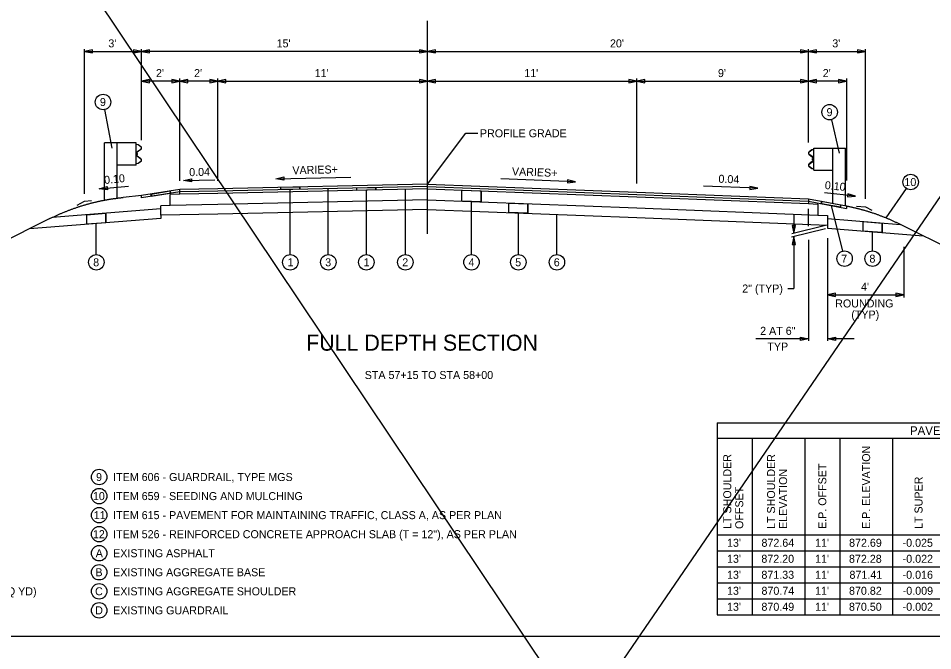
# Model space of a CAD drawing. Extents: x -345 to 102, y -108 to 100.
# Drawn here: x -306.37 to -258.37, y -8.45 to 24.76 of the extents above; entities that cross this region are included whole.
import ezdxf

# ---------------------------------------------------------------- set-up
doc = ezdxf.new("R2010")
doc.units = 0
for name, color, linetype in [('RD_P_Cells', 7, 'Continuous'), ('SH_Border', 7, 'Continuous'), ('SH_Data', 7, 'Continuous'), ('SH_Text', 7, 'Continuous'), ('TX_P_1', 7, 'Continuous'), ('TX_X_1', 7, 'Continuous'), ('XS_P_Finished_Grade', 7, 'Continuous'), ('XS_P_Pavt_Surface', 7, 'Continuous')]:
    doc.layers.add(name, color=color, linetype=linetype)

msp = doc.modelspace()

# ---------------------------------------------------------------- linework, layer by layer
at = {"layer": 'RD_P_Cells'}
for p, q in [((-301.175, 18.213), (-301.842, 18.213)), ((-301.842, 15.21), (-301.842, 18.213)), ((-300.175, 18.213), (-301.175, 18.213)), ((-301.175, 15.315), (-301.175, 18.213)), ((-300.175, 17.046), (-300.175, 18.213)), ((-300.16, 18.141), (-300.16, 18.141)), ((-300.16, 18.141), (-300.073, 18.126)), ((-300.16, 18.131), (-300.16, 18.141)), ((-300.16, 18.131), (-300.16, 18.131)), ((-300.077, 18.117), (-300.16, 18.131)), ((-300.123, 17.747), (-299.936, 17.885)), ((-299.93, 17.877), (-300.117, 17.739)), ((-300.077, 18.117), (-300.077, 18.117)), ((-299.936, 18.011), (-300.077, 18.117)), ((-300.073, 18.126), (-300.073, 18.126)), ((-300.073, 18.126), (-299.93, 18.019)), ((-300.056, 17.797), (-300.056, 17.797)), ((-300.055, 18.101), (-300.055, 18.101)), ((-300.05, 18.109), (-300.05, 18.109)), ((-300.05, 17.789), (-300.05, 17.789)), ((-299.936, 18.011), (-299.936, 18.011)), ((-299.936, 17.885), (-299.936, 17.885)), ((-299.93, 18.019), (-299.93, 18.019)), ((-299.93, 17.877), (-299.93, 17.877)), ((-299.904, 17.948), (-299.904, 17.948)), ((-299.894, 17.948), (-299.894, 17.948)), ((-264.715, 17.856), (-264.859, 17.749)), ((-264.853, 17.741), (-264.711, 17.847)), ((-264.739, 17.838), (-264.739, 17.838)), ((-264.733, 17.831), (-264.733, 17.831)), ((-264.628, 17.871), (-264.715, 17.856)), ((-264.715, 17.856), (-264.715, 17.856)), ((-264.711, 17.847), (-264.628, 17.861)), ((-264.711, 17.847), (-264.711, 17.847)), ((-264.628, 17.871), (-264.628, 17.871)), ((-264.628, 17.861), (-264.628, 17.871)), ((-264.628, 17.861), (-264.628, 17.861)), ((-264.613, 17.943), (-263.613, 17.943)), ((-264.613, 16.776), (-264.613, 17.943)), ((-263.613, 17.943), (-262.946, 17.943)), ((-263.613, 15.038), (-263.613, 17.943)), ((-262.946, 14.913), (-262.946, 17.943)), ((-300.159, 17.676), (-300.159, 17.676)), ((-300.159, 17.584), (-300.159, 17.676)), ((-300.159, 17.598), (-300.159, 17.661)), ((-300.159, 17.584), (-300.159, 17.584)), ((-300.15, 17.676), (-300.15, 17.676)), ((-300.15, 17.676), (-300.149, 17.584)), ((-300.149, 17.598), (-300.149, 17.661)), ((-300.149, 17.584), (-300.149, 17.584)), ((-300.123, 17.747), (-300.123, 17.747)), ((-300.123, 17.512), (-300.123, 17.512)), ((-299.935, 17.375), (-300.123, 17.512)), ((-300.117, 17.739), (-300.117, 17.739)), ((-300.117, 17.52), (-300.117, 17.52)), ((-300.117, 17.52), (-299.929, 17.383)), ((-299.935, 17.375), (-299.935, 17.375)), ((-299.929, 17.383), (-299.929, 17.383)), ((-299.903, 17.312), (-299.903, 17.312)), ((-299.893, 17.312), (-299.893, 17.312)), ((-264.894, 17.678), (-264.894, 17.678)), ((-264.884, 17.678), (-264.884, 17.678)), ((-264.859, 17.749), (-264.859, 17.749)), ((-264.858, 17.606), (-264.858, 17.606)), ((-264.858, 17.606), (-264.671, 17.469)), ((-264.853, 17.741), (-264.853, 17.741)), ((-264.852, 17.614), (-264.852, 17.614)), ((-264.665, 17.477), (-264.852, 17.614)), ((-264.738, 17.518), (-264.738, 17.518)), ((-264.732, 17.526), (-264.732, 17.526)), ((-264.671, 17.469), (-264.671, 17.469)), ((-264.665, 17.477), (-264.665, 17.477)), ((-264.639, 17.405), (-264.639, 17.405)), ((-264.639, 17.405), (-264.639, 17.313)), ((-264.639, 17.328), (-264.639, 17.391)), ((-264.639, 17.313), (-264.639, 17.313)), ((-264.629, 17.405), (-264.629, 17.405)), ((-264.629, 17.313), (-264.629, 17.405)), ((-264.629, 17.328), (-264.629, 17.391)), ((-264.629, 17.313), (-264.629, 17.313)), ((-300.175, 17.046), (-301.175, 17.046)), ((-300.158, 17.128), (-300.075, 17.143)), ((-300.071, 17.133), (-300.158, 17.118)), ((-300.158, 17.128), (-300.158, 17.128)), ((-300.158, 17.118), (-300.158, 17.128)), ((-300.158, 17.118), (-300.158, 17.118)), ((-300.075, 17.143), (-299.934, 17.249)), ((-299.928, 17.241), (-300.071, 17.133)), ((-299.934, 17.249), (-299.934, 17.249)), ((-299.928, 17.241), (-299.928, 17.241)), ((-264.895, 17.042), (-264.895, 17.042)), ((-264.885, 17.042), (-264.885, 17.042)), ((-264.86, 16.971), (-264.86, 16.971)), ((-264.86, 16.971), (-264.717, 16.863)), ((-264.671, 17.25), (-264.859, 17.113)), ((-264.859, 17.113), (-264.859, 17.113)), ((-264.854, 16.978), (-264.854, 16.978)), ((-264.713, 16.872), (-264.854, 16.978)), ((-264.853, 17.105), (-264.665, 17.242)), ((-264.853, 17.105), (-264.853, 17.105)), ((-264.717, 16.863), (-264.63, 16.848)), ((-264.63, 16.858), (-264.713, 16.872)), ((-264.671, 17.25), (-264.671, 17.25)), ((-264.665, 17.242), (-264.665, 17.242)), ((-264.63, 16.858), (-264.63, 16.858)), ((-264.63, 16.848), (-264.63, 16.858)), ((-264.63, 16.848), (-264.63, 16.848)), ((-264.613, 16.776), (-263.613, 16.776))]:
    msp.add_line(p, q, dxfattribs=at)
for points in [[(-300.141, 17.69), (-300.141, 17.57), (-300.149, 17.57), (-300.149, 17.69)], [(-300.141, 17.658), (-300.141, 17.6), (-300.116, 17.6), (-300.116, 17.658)], [(-264.647, 17.388), (-264.647, 17.329), (-264.672, 17.329), (-264.672, 17.388)], [(-264.647, 17.419), (-264.647, 17.299), (-264.639, 17.299), (-264.639, 17.419)]]:
    msp.add_lwpolyline(points, close=True, dxfattribs=at)
for centre, radius, start, end in [((-299.983, 17.948), 0.0787, 306.318, 53.2212), ((-299.983, 17.948), 0.0886, 306.318, 53.2212), ((-300.071, 17.676), 0.0886, 126.318, 180.0944), ((-300.071, 17.584), 0.0886, 180.0944, 233.8707), ((-300.071, 17.676), 0.0788, 126.318, 180.0944), ((-300.071, 17.584), 0.0788, 180.0944, 233.8707), ((-299.982, 17.312), 0.0787, 306.9675, 53.8707), ((-299.982, 17.312), 0.0886, 306.9675, 53.8707), ((-264.805, 17.678), 0.0886, 126.7788, 233.682), ((-264.805, 17.678), 0.0787, 126.7788, 233.682), ((-264.717, 17.405), 0.0788, 359.9056, 53.682), ((-264.718, 17.314), 0.0788, 306.1293, 359.9056), ((-264.717, 17.405), 0.0886, 359.9056, 53.682), ((-264.718, 17.314), 0.0886, 306.1293, 359.9056), ((-264.807, 17.041), 0.0886, 126.1293, 233.0325), ((-264.807, 17.041), 0.0787, 126.1293, 233.0325)]:
    msp.add_arc(centre, radius, start, end, dxfattribs=at)
at = {"layer": 'SH_Border'}
msp.add_lwpolyline([(-330.644, 55.298), (-234.644, 55.298), (-234.644, -7.702), (-330.644, -7.702)], close=True, dxfattribs=at)
at = {"layer": 'TX_P_1'}
for p, q in [((-302.894, 15.533), (-302.894, 23.137)), ((-302.474, 22.938), (-302.474, 23.106)), ((-300.314, 23.106), (-300.314, 22.938)), ((-299.894, 18.358), (-299.894, 23.137)), ((-299.474, 22.938), (-299.474, 23.106)), ((-285.314, 23.106), (-285.314, 22.938)), ((-284.474, 22.938), (-284.474, 23.106)), ((-265.314, 23.106), (-265.314, 22.938)), ((-264.894, 18.228), (-264.894, 23.137)), ((-264.474, 22.938), (-264.474, 23.106)), ((-262.314, 23.106), (-262.314, 22.938)), ((-261.894, 15.285), (-261.894, 23.137)), ((-302.894, 23.022), (-299.894, 23.022)), ((-284.894, 23.022), (-299.894, 23.022)), ((-284.894, 23.022), (-264.894, 23.022)), ((-264.894, 23.022), (-261.894, 23.022)), ((-297.894, 21.462), (-299.894, 21.462)), ((-299.474, 21.378), (-299.474, 21.546)), ((-298.314, 21.546), (-298.314, 21.378)), ((-297.894, 16.216), (-297.894, 21.591)), ((-295.894, 21.462), (-297.894, 21.462)), ((-297.474, 21.378), (-297.474, 21.546)), ((-296.314, 21.546), (-296.314, 21.378)), ((-295.894, 16.231), (-295.894, 21.591)), ((-295.894, 21.462), (-284.894, 21.462)), ((-295.474, 21.378), (-295.474, 21.546)), ((-285.314, 21.546), (-285.314, 21.378)), ((-285.314, 21.546), (-285.314, 21.378)), ((-284.894, 21.462), (-273.894, 21.462)), ((-284.474, 21.378), (-284.474, 21.546)), ((-274.314, 21.546), (-274.314, 21.378)), ((-274.314, 21.546), (-274.314, 21.378)), ((-273.894, 16.086), (-273.894, 21.591)), ((-273.894, 21.462), (-264.894, 21.462)), ((-273.474, 21.378), (-273.474, 21.546)), ((-265.314, 21.546), (-265.314, 21.378)), ((-262.894, 21.462), (-264.894, 21.462)), ((-264.474, 21.378), (-264.474, 21.546)), ((-263.314, 21.546), (-263.314, 21.378)), ((-262.894, 21.591), (-262.894, 16.245)), ((-284.894, 16.054), (-282.875, 18.72)), ((-282.875, 18.72), (-282.25, 18.72)), ((-297.28, 16.331), (-297.277, 16.163)), ((-292.848, 16.337), (-288.92, 16.424)), ((-292.429, 16.43), (-292.426, 16.262)), ((-277.119, 16.179), (-281.045, 16.328)), ((-302.12, 15.796), (-300.585, 15.949)), ((-301.711, 15.921), (-301.694, 15.754)), ((-297.698, 16.239), (-296.05, 16.272)), ((-277.535, 16.279), (-277.542, 16.111)), ((-267.548, 15.833), (-270.402, 15.948)), ((-267.964, 15.934), (-267.971, 15.766)), ((-262.414, 15.422), (-264.051, 15.586)), ((-262.823, 15.548), (-262.84, 15.381)), ((-298.894, 14.754), (-304.59, 14.298)), ((-298.894, 14.419), (-298.894, 14.252)), ((-265.664, 14.438), (-265.664, 13.465)), ((-264.894, 13.838), (-264.894, 14.747)), ((-298.894, 14.252), (-305.787, 13.701)), ((-263.894, 14.238), (-260.053, 13.931)), ((-264.003, 13.709), (-265.778, 13.27)), ((-264.003, 13.876), (-265.757, 13.441)), ((-265.58, 13.885), (-265.748, 13.885)), ((-263.894, 13.903), (-263.894, 13.736)), ((-263.894, 13.736), (-258.858, 13.334)), ((-265.664, 13.298), (-265.664, 10.569)), ((-264.894, 13.133), (-264.894, 7.819)), ((-263.894, 13.212), (-263.894, 7.819)), ((-265.748, 12.878), (-265.58, 12.878)), ((-259.894, 12.76), (-259.894, 10.097)), ((-265.983, 10.569), (-265.664, 10.569)), ((-263.894, 10.241), (-259.894, 10.241)), ((-263.474, 10.157), (-263.474, 10.325)), ((-260.314, 10.325), (-260.314, 10.157)), ((-264.894, 7.926), (-267.663, 7.926)), ((-265.314, 7.842), (-265.314, 8.01)), ((-262.492, 7.926), (-263.894, 7.926)), ((-263.474, 8.01), (-263.474, 7.842)), ((-269.689, 3.507), (-269.689, -6.564)), ((-269.689, 3.507), (-240.289, 3.507)), ((-269.689, 2.707), (-240.289, 2.707)), ((-267.839, 2.707), (-267.839, -6.564)), ((-265.089, 2.707), (-265.089, -6.564)), ((-263.239, 2.707), (-263.239, -6.564)), ((-260.489, 2.707), (-260.489, -6.564)), ((-269.689, -2.364), (-240.289, -2.364)), ((-269.689, -3.204), (-240.289, -3.204)), ((-269.689, -4.044), (-240.289, -4.044)), ((-269.689, -4.884), (-240.289, -4.884)), ((-269.689, -5.724), (-240.289, -5.724)), ((-269.689, -6.564), (-240.289, -6.564))]:
    msp.add_line(p, q, dxfattribs=at)
for points in [[(-302.474, 23.106), (-302.894, 23.022), (-302.474, 22.938)], [(-300.314, 22.938), (-299.894, 23.022), (-300.314, 23.106)], [(-299.474, 23.106), (-299.894, 23.022), (-299.474, 22.938)], [(-285.314, 22.938), (-284.894, 23.022), (-285.314, 23.106)], [(-284.474, 23.106), (-284.894, 23.022), (-284.474, 22.938)], [(-265.314, 22.938), (-264.894, 23.022), (-265.314, 23.106)], [(-264.474, 23.106), (-264.894, 23.022), (-264.474, 22.938)], [(-262.314, 22.938), (-261.894, 23.022), (-262.314, 23.106)], [(-299.474, 21.546), (-299.894, 21.462), (-299.474, 21.378)], [(-298.314, 21.378), (-297.894, 21.462), (-298.314, 21.546)], [(-297.474, 21.546), (-297.894, 21.462), (-297.474, 21.378)], [(-296.314, 21.378), (-295.894, 21.462), (-296.314, 21.546)], [(-295.474, 21.546), (-295.894, 21.462), (-295.474, 21.378)], [(-285.314, 21.378), (-284.894, 21.462), (-285.314, 21.546)], [(-285.314, 21.378), (-284.894, 21.462), (-285.314, 21.546)], [(-284.474, 21.546), (-284.894, 21.462), (-284.474, 21.378)], [(-274.314, 21.378), (-273.894, 21.462), (-274.314, 21.546)], [(-274.314, 21.378), (-273.894, 21.462), (-274.314, 21.546)], [(-273.474, 21.546), (-273.894, 21.462), (-273.474, 21.378)], [(-265.314, 21.378), (-264.894, 21.462), (-265.314, 21.546)], [(-264.474, 21.546), (-264.894, 21.462), (-264.474, 21.378)], [(-263.314, 21.378), (-262.894, 21.462), (-263.314, 21.546)], [(-297.277, 16.163), (-297.698, 16.239), (-297.28, 16.331)], [(-292.426, 16.262), (-292.848, 16.337), (-292.429, 16.43)], [(-301.694, 15.754), (-302.12, 15.796), (-301.711, 15.921)], [(-277.542, 16.111), (-277.119, 16.179), (-277.535, 16.279)], [(-267.971, 15.766), (-267.548, 15.833), (-267.964, 15.934)], [(-262.84, 15.381), (-262.414, 15.422), (-262.823, 15.548)], [(-303.284, 14.953), (-302.894, 15.147), (-302.519, 15.185)], [(-262.367, 14.899), (-261.894, 14.851), (-261.569, 14.689)], [(-265.748, 13.885), (-265.664, 13.465), (-265.58, 13.885)], [(-265.58, 12.878), (-265.664, 13.298), (-265.748, 12.878)], [(-263.474, 10.325), (-263.894, 10.241), (-263.474, 10.157)], [(-260.314, 10.157), (-259.894, 10.241), (-260.314, 10.325)], [(-265.314, 8.01), (-264.894, 7.926), (-265.314, 7.842)], [(-263.474, 7.842), (-263.894, 7.926), (-263.474, 8.01)]]:
    msp.add_lwpolyline(points, dxfattribs=at)
for points in [[(-292.591, 15.76), (-292.591, 15.885), (-291.591, 15.907), (-291.591, 15.782)], [(-288.6, 15.723), (-288.6, 15.848), (-287.6, 15.87), (-287.6, 15.745)], [(-299.4, 15.403), (-299.4, 15.528), (-298.4, 15.69), (-298.4, 15.565)], [(-282.079, 15.114), (-283.079, 15.152), (-283.079, 15.735), (-282.079, 15.697)], [(-279.619, 15.021), (-279.619, 14.521), (-280.619, 14.559), (-280.619, 15.059)], [(-301.773, 14.524), (-301.773, 14.022), (-302.773, 13.942), (-302.773, 14.444)]]:
    msp.add_lwpolyline(points, close=True, dxfattribs=at)
for centre in [(-301.922, 20.362), (-263.78, 19.83), (-259.527, 16.159), (-262.995, 12.138), (-261.526, 12.138), (-302.273, 11.946), (-292.091, 11.946), (-290.095, 11.946), (-288.1, 11.946), (-286.05, 11.946), (-282.579, 11.946), (-280.119, 11.946), (-278.096, 11.946), (-302.125, 0.668), (-302.125, -0.332), (-302.125, -1.332), (-302.125, -2.332), (-302.125, -3.332), (-302.125, -4.332), (-302.125, -5.332), (-302.125, -6.332)]:
    msp.add_circle(centre, 0.406, dxfattribs=at)
at = {"layer": 'TX_X_1'}
for p, q in [((-200.323, 99.689), (-335.9, -98.481)), ((-344.901, 89.556), (-212.699, -108.052)), ((-284.894, 13.44), (-284.894, 24.619)), ((-301.844, 19.963), (-301.451, 17.94)), ((-263.689, 19.434), (-263.287, 17.68)), ((-292.591, 15.76), (-292.591, 15.885)), ((-291.591, 15.782), (-291.591, 15.907)), ((-288.6, 15.723), (-288.6, 15.848)), ((-287.6, 15.745), (-287.6, 15.87)), ((-299.4, 15.528), (-299.4, 15.403)), ((-292.091, 12.353), (-292.091, 15.771)), ((-290.095, 12.353), (-290.095, 15.815)), ((-288.1, 12.353), (-288.1, 15.734)), ((-286.05, 12.353), (-286.05, 15.779)), ((-283.079, 15.152), (-283.079, 15.735)), ((-282.079, 15.114), (-282.079, 15.697)), ((-259.759, 15.825), (-260.83, 14.285)), ((-282.579, 12.353), (-282.579, 15.133)), ((-280.619, 14.559), (-280.619, 15.059)), ((-279.619, 14.521), (-279.619, 15.021)), ((-264.208, 15.148), (-264.208, 15.023)), ((-263.094, 12.532), (-263.69, 14.927)), ((-263.208, 14.962), (-263.208, 14.837)), ((-302.773, 13.942), (-302.773, 14.444)), ((-301.773, 14.022), (-301.773, 14.524)), ((-280.119, 12.353), (-280.119, 14.54)), ((-278.096, 12.353), (-278.096, 14.463)), ((-302.273, 12.353), (-302.273, 13.982)), ((-262.026, 13.587), (-262.026, 14.089)), ((-261.026, 13.507), (-261.026, 14.009)), ((-261.526, 12.544), (-261.526, 13.547))]:
    msp.add_line(p, q, dxfattribs=at)
for points in [[(-263.208, 14.837), (-264.208, 15.023), (-264.208, 15.148), (-263.208, 14.962)], [(-261.026, 14.009), (-261.026, 13.507), (-262.026, 13.587), (-262.026, 14.089)]]:
    msp.add_lwpolyline(points, close=True, dxfattribs=at)
at = {"layer": 'XS_P_Finished_Grade'}
for p, q in [((-299.894, 15.447), (-300.871, 15.35)), ((-304.713, 14.238), (-314.593, 9.298)), ((-260.075, 13.942), (-255.838, 11.823))]:
    msp.add_line(p, q, dxfattribs=at)
for points in [[(-304.713, 14.238), (-304.643, 14.273), (-304.573, 14.307), (-304.502, 14.341), (-304.432, 14.374), (-304.361, 14.406), (-304.29, 14.438), (-304.22, 14.47), (-304.148, 14.501), (-304.077, 14.532), (-304.006, 14.562), (-303.934, 14.591), (-303.863, 14.62), (-303.791, 14.649), (-303.719, 14.676), (-303.647, 14.704), (-303.574, 14.731), (-303.502, 14.757), (-303.429, 14.783), (-303.356, 14.808), (-303.284, 14.833), (-303.21, 14.857), (-303.137, 14.881), (-303.064, 14.904), (-302.99, 14.927), (-302.917, 14.949), (-302.843, 14.971), (-302.769, 14.992), (-302.695, 15.012), (-302.621, 15.032), (-302.546, 15.052), (-302.472, 15.071), (-302.397, 15.09), (-302.322, 15.108), (-302.247, 15.125), (-302.172, 15.142), (-302.096, 15.158), (-302.021, 15.174), (-301.945, 15.19), (-301.87, 15.204), (-301.794, 15.219), (-301.718, 15.233), (-301.641, 15.246), (-301.565, 15.259), (-301.488, 15.271), (-301.412, 15.282), (-301.335, 15.294), (-301.258, 15.304), (-301.181, 15.314), (-301.103, 15.324), (-301.026, 15.333), (-300.948, 15.342), (-300.871, 15.35)], [(-262.894, 14.904), (-262.843, 14.894), (-262.767, 14.878), (-262.692, 14.862), (-262.616, 14.846), (-262.541, 14.829), (-262.466, 14.812), (-262.391, 14.794), (-262.317, 14.775), (-262.242, 14.756), (-262.168, 14.736), (-262.093, 14.716), (-262.019, 14.696), (-261.945, 14.675), (-261.871, 14.653), (-261.798, 14.631), (-261.724, 14.608), (-261.651, 14.585), (-261.578, 14.561), (-261.505, 14.537), (-261.432, 14.512), (-261.359, 14.487), (-261.286, 14.461), (-261.214, 14.435), (-261.142, 14.408), (-261.069, 14.38), (-260.997, 14.353), (-260.926, 14.324), (-260.854, 14.295), (-260.782, 14.266), (-260.711, 14.236), (-260.64, 14.205), (-260.569, 14.174), (-260.498, 14.142), (-260.427, 14.11), (-260.356, 14.078), (-260.286, 14.045), (-260.215, 14.011), (-260.145, 13.977), (-260.075, 13.942)]]:
    msp.add_spline(points, degree=3, dxfattribs=at)
at = {"layer": 'XS_P_Pavt_Surface'}
for p, q in [((-284.894, 16.054), (-295.894, 15.812)), ((-284.894, 15.929), (-295.894, 15.687)), ((-284.894, 16.054), (-273.894, 15.636)), ((-284.894, 15.929), (-273.894, 15.511)), ((-297.894, 15.772), (-299.894, 15.447)), ((-297.894, 15.647), (-299.894, 15.322)), ((-299.894, 15.322), (-299.894, 15.447)), ((-297.894, 15.522), (-298.394, 15.512)), ((-298.394, 14.929), (-298.394, 15.512)), ((-295.894, 15.812), (-297.894, 15.772)), ((-297.894, 15.522), (-297.894, 15.772)), ((-295.894, 15.687), (-297.894, 15.647)), ((-295.894, 15.562), (-297.894, 15.522)), ((-284.894, 15.804), (-295.894, 15.562)), ((-284.894, 15.804), (-273.894, 15.386)), ((-273.894, 15.636), (-264.894, 15.276)), ((-273.894, 15.511), (-264.894, 15.151)), ((-273.894, 15.386), (-264.894, 15.026)), ((-298.394, 14.929), (-298.894, 14.919)), ((-298.894, 14.419), (-298.894, 14.919)), ((-295.894, 14.979), (-298.394, 14.929)), ((-284.894, 15.221), (-295.894, 14.979)), ((-284.894, 15.221), (-273.894, 14.803)), ((-264.894, 15.276), (-262.894, 14.904)), ((-264.894, 15.264), (-264.894, 15.026)), ((-264.894, 15.151), (-262.894, 14.779)), ((-264.894, 15.026), (-264.394, 15.006)), ((-264.394, 15.006), (-264.394, 14.423)), ((-262.894, 14.904), (-262.894, 14.779)), ((-295.894, 14.479), (-298.894, 14.419)), ((-284.894, 14.721), (-295.894, 14.479)), ((-284.894, 14.721), (-273.894, 14.303)), ((-273.894, 14.803), (-264.394, 14.423)), ((-264.394, 14.423), (-263.894, 14.403)), ((-263.894, 14.403), (-263.894, 13.903)), ((-273.894, 14.303), (-263.894, 13.903))]:
    msp.add_line(p, q, dxfattribs=at)

# ---------------------------------------------------------------- texts
at = {"layer": 'SH_Data'}
msp.add_text('PAVEMENT ELEVATION TABLE', height=0.45, dxfattribs=at).set_placement((-259.564, 2.882))
at = {"layer": 'SH_Text'}
msp.add_text('FULL DEPTH SECTION', height=0.84, dxfattribs=at).set_placement((-291.26, 7.304))
at = {"layer": 'TX_P_1'}
for s, p in [("3'", (-301.642, 23.232)), ("15'", (-292.81, 23.232)), ("20'", (-275.31, 23.232)), ("3'", (-263.642, 23.232)), ("2'", (-299.142, 21.672)), ("2'", (-297.142, 21.672)), ("11'", (-290.81, 21.672)), ("11'", (-279.81, 21.672)), ("9'", (-269.642, 21.672)), ("2'", (-264.142, 21.672)), ('9', (-302.084, 20.152)), ('9', (-263.942, 19.62)), ('PROFILE GRADE', (-282.138, 18.51)), ('10', (-259.856, 15.949)), ('8', (-302.438, 11.736)), ('1', (-292.231, 11.736)), ('3', (-290.259, 11.736)), ('1', (-288.241, 11.736)), ('2', (-286.215, 11.736)), ('4', (-282.738, 11.736)), ('5', (-280.287, 11.736)), ('6', (-278.262, 11.736)), ('7', (-263.17, 11.928)), ('8', (-261.691, 11.928)), ('2" (TYP)', (-268.367, 10.359)), ("4'", (-262.133, 10.451)), ('ROUNDING', (-263.488, 9.575)), ('(TYP)', (-262.643, 8.994)), ('2 AT 6"', (-267.427, 8.136)), ('TYP', (-267.05, 7.309)), ('STA 57+15 TO STA 58+00', (-288.184, 5.818)), ('9', (-302.287, 0.458)), ('ITEM 606 - GUARDRAIL, TYPE MGS', (-301.39, 0.458)), ('10', (-302.454, -0.542)), ('ITEM 659 - SEEDING AND MULCHING', (-301.39, -0.542)), ('11', (-302.407, -1.542)), ('ITEM 615 - PAVEMENT FOR MAINTAINING TRAFFIC, CLASS A, AS PER PLAN', (-301.39, -1.542)), ('12', (-302.453, -2.542)), ('ITEM 526 - REINFORCED CONCRETE APPROACH SLAB (T = 12"), AS PER PLAN', (-301.39, -2.542)), ("13'", (-269.166, -2.994)), ('872.64', (-267.358, -2.994)), ("11'", (-264.544, -2.994)), ('872.69', (-262.76, -2.994)), ('-0.025', (-259.95, -2.994)), ('A', (-302.306, -3.542)), ('EXISTING ASPHALT', (-301.39, -3.542)), ("13'", (-269.166, -3.834)), ('872.20', (-267.364, -3.834)), ("11'", (-264.544, -3.834)), ('872.28', (-262.764, -3.834)), ('-0.022', (-259.947, -3.834)), ('B', (-302.321, -4.542)), ('EXISTING AGGREGATE BASE', (-301.39, -4.542)), ("13'", (-269.166, -4.674)), ('871.33', (-267.362, -4.674)), ("11'", (-264.544, -4.674)), ('871.41', (-262.739, -4.674)), ('-0.016', (-259.949, -4.674)), ('ITEM 617 - 1.5" COMPACTED AGGREGATE & ITEM 408 - PRIME COAT (0.4 GAL/SQ YD)', (-328.392, -5.542)), ('C', (-302.339, -5.542)), ('EXISTING AGGREGATE SHOULDER', (-301.39, -5.542)), ("13'", (-269.166, -5.514)), ('870.74', (-267.358, -5.514)), ("11'", (-264.544, -5.514)), ('870.82', (-262.763, -5.514)), ('-0.009', (-259.944, -5.514)), ('D', (-302.334, -6.542)), ('EXISTING GUARDRAIL', (-301.39, -6.542)), ("13'", (-269.166, -6.354)), ('870.49', (-267.36, -6.354)), ("11'", (-264.544, -6.354)), ('870.50', (-262.764, -6.354)), ('-0.002', (-259.947, -6.354))]:
    msp.add_text(s, height=0.42, dxfattribs=at).set_placement(p)
for s, rotation, p in [('0.04', 1.1458, (-297.395, 16.467)), ('VARIES+', 1.2603, (-291.978, 16.566)), ('VARIES+', 357.8238, (-280.463, 16.516)), ('0.04', 357.7094, (-269.623, 16.127)), ('E.P. ELEVATION', 90, (-261.654, -2.057)), ('LT SHOULDER', 90, (-268.944, -2.057)), ('LT SHOULDER', 90, (-266.644, -2.057)), ('ELEVATION', 90, (-266.014, -2.057)), ('E.P. OFFSET', 90, (-263.954, -2.057)), ('LT SUPER', 90, (-258.904, -2.057)), ('OFFSET', 90, (-268.314, -2.057))]:
    msp.add_text(s, height=0.42, rotation=rotation, dxfattribs=at).set_placement(p)
at = {"layer": 'XS_P_Finished_Grade'}
for rotation, p in [(5.7106, (-301.844, 16.054)), (354.2894, (-264.049, 15.797))]:
    msp.add_text('0.10', height=0.42, rotation=rotation, dxfattribs=at).set_placement(p)

doc.saveas('drawing.dxf')
